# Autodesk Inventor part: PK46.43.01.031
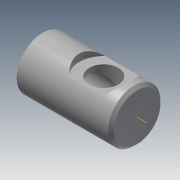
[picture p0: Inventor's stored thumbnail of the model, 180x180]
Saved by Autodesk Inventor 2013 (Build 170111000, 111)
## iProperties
Shininess: 64.0
Length Units: 11269
Angle Units: 11279
Time Units: 11290
Mass Units: 11283
Length Display Precision: 3
Angle Display Precision: 2
Compacted: True
Part Number: PK46.43.01.031
Document SubType Name: Modeling
Created: 2004-12
Material: Steel, Mild
Designer: ELarisa
Manufacturer: Standard
Standards Organization: Custom
Density: 7.86 g/cm^3
Density: 0.0
Volumn: 0.0
Area: 0.0
PropertySet Name: Model Information
Control State: 0
Master: False
Checked Out: False
Checked Out Date: 2008-10-09
Last Check In Date: 2008-10-09
Author: ELarisa
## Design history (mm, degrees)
sketch "Эскиз1"
  geometry: L1 (-35.076, -2.38)-(-35.076, 15.62); L2 (-35.076, 15.62)-(29.924, 15.62); L3 (29.924, 15.62)-(29.924, -2.38); L4 (29.924, -2.38)-(-35.076, -2.38); L5 (-35.076, 7.62)-(18.924, 7.62); L6 (18.924, 7.62)-(24.698, -2.38)
  constraints: 12 end point, 2 parallel, 2 point on line, 1 perpendicular, 1 vertical
  dimensions: "d0" = 65 distance of L3.end L1.start; "d1" = 18 distance of L2.end L3.end; "d3" = 10 distance between parallel lines of L4 L5; "d4" = 120 deg angle of L6 L5; "d6" = 54 distance of L5.start L5.end
revolve "Вращение1" sketch "Эскиз1" stored, may be unused: angle "d7" = 90 deg
node "РабОсь1"
node "РабПлоскость1"
sketch "Эскиз2"
  geometry: L1 (-48.076, -2.38)-(42.924, -2.38) reference; L2 (-35.076, -18.88)-(-35.076, 14.12) reference; L3 (29.924, -20.38)-(29.924, 15.62) reference; L4 (-35.076, -20.38)-(29.924, -20.38) reference; L5 (-35.076, -20.38)-(-35.076, 15.62) reference; 1 further point
  dimensions: "d9" = 0 distance from line of L1 point (6.924, -2.38); "d21" = 42 distance from line of L5 point (6.924, -2.38)
hole "Отверстие1" sketch "Эскиз2" diameter "d11" = 20; stored, may be unused: countersink angle "d15" = 82 deg, drill point angle "d17" = 118 deg; dims "d12" = 6, "d13" = 34, "d14" = 5, "d16" = 18
chamfer "Фаска1" distance "d18" = 2; stored, may be unused: second distance "d19" = 2, angle "d20" = 45 deg
body "Solid1"
other parameters: "d8" = 18
